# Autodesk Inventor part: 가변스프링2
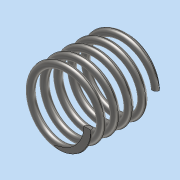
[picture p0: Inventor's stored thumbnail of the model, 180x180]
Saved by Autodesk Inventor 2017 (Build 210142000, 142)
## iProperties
Part Number: 가변스프링2
Material: 스테인레스 스틸
Document SubType Name: Modeling
Designer: MRC
Density: 8 g/cm^3
Appearance: 반연마
Mass: 6.96277 g
Surface Area: 17.6923 cm^2
Volume: 0.870346 cm^3
Author: MRC
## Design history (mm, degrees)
sketch "스케치1"
  geometry: L1 (0, 0)-(0, 19.5); L2 (0, 0)-(9, 0); L3 (0, 19.5)-(9, 19.5); C1 r 1 at (9, 0)
  constraints: 6 end point, 2 horizontal, 1 centre point, 1 coincident, 1 vertical
  dimensions: "d0" = 19.5 distance of L1.start L1.end (derived); "d1" = 9 distance of L1.start L2.end; "d2" = 9 distance of L1.end L3.end; "d3" = 2 diameter of C1
feature "코일1" sketch "스케치1" pitch "d4" = 10; turns "d6" = 5; dims "d5" = 19.5 (= d0), "d7" = 0, angle "d8" = 90 deg, angle "d9" = 90 deg, "d10" = 0, "d11" = 0
sketch "스케치2"
  geometry: L1 (19.5, 16.059)-(0, 16.059); L2 (0, 16.059)-(0, -16.059); L3 (0, -16.059)-(19.5, -16.059); L4 (19.5, -16.059)-(19.5, 16.059); 2 further points
  constraints: 8 end point, 2 parallel, 1 coincident, 1 horizontal, 1 midpoint, 1 perpendicular
  dimensions: "d12" = 19.5 distance of L2.end L3.end (= d0); "d13" = 32.11845 distance of L3.end L1.start
extrude "돌출1" sketch "스케치2" stored distance "d14" = 0; taper "d15" = 0 deg
node "솔리드1"
